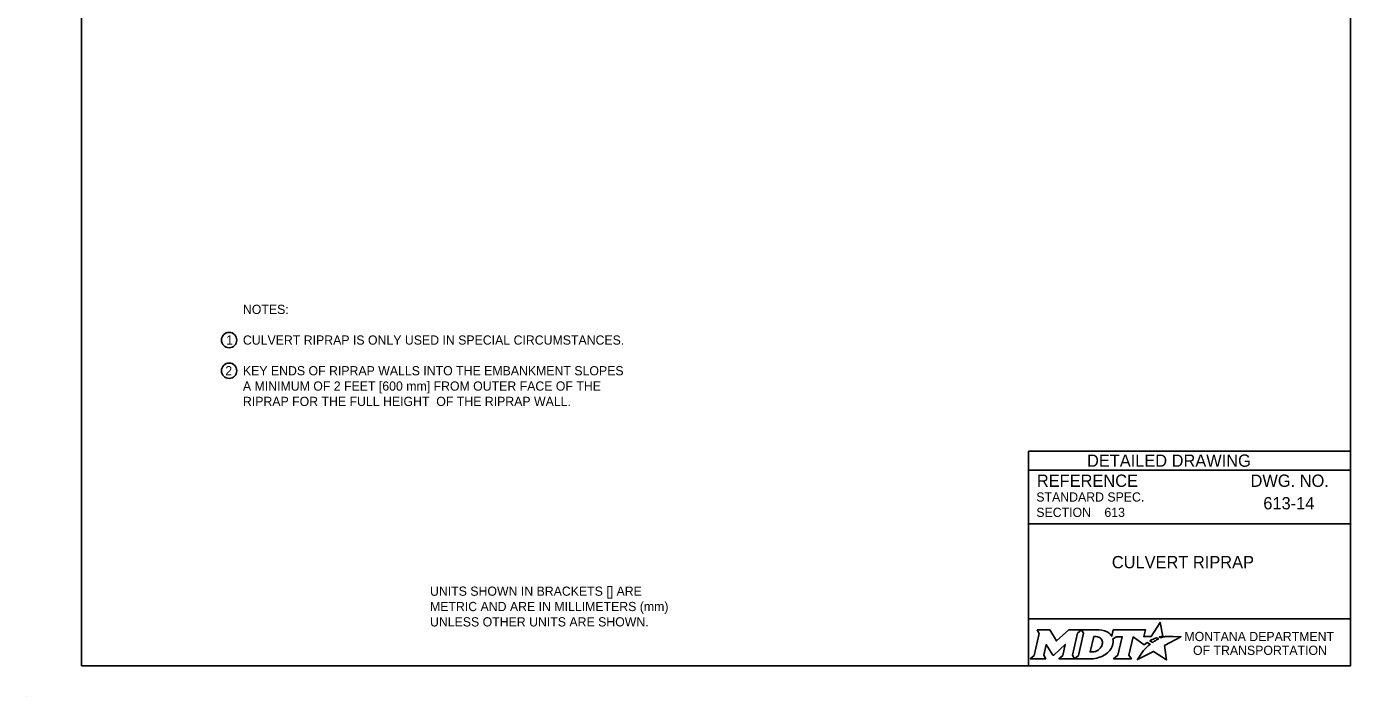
# Model space of a CAD drawing. Extents: x 49991.4 to 50021, y 49987.6 to 50011.4.
# Drawn here: x 49999.98 to 50008.61, y 49999.86 to 50004.23 of the extents above; entities that cross this region are included whole.
import ezdxf

# ---------------------------------------------------------------- set-up
doc = ezdxf.new("R2010")
doc.units = 0
doc.layers.add('Level 1', color=7, linetype='Continuous')
doc.layers.add('Level 2', color=7, linetype='Continuous')

msp = doc.modelspace()

# ---------------------------------------------------------------- linework, layer by layer
at = {"layer": 'Level 1'}
msp.add_line((49999.9766, 49999.8624), (49999.9766, 49999.8624), dxfattribs=at)
msp.add_lwpolyline([(50008.6146, 50011.2628), (50000.3356, 50011.2628), (50000.3356, 50000.0624), (50008.6146, 50000.0624)], close=True, dxfattribs=at)
at = {"layer": 'Level 2'}
for p, q in [((50008.6146, 50001.4624), (50006.5146, 50001.4624)), ((50006.5146, 50001.4624), (50006.5146, 50000.0624)), ((50008.6146, 50001.3374), (50006.5146, 50001.3374)), ((50008.2507, 50001.1223), (50008.2507, 50001.1223)), ((50008.6146, 50000.9874), (50006.5146, 50000.9874)), ((50007.0089, 50001.0629), (50007.0089, 50001.0629)), ((50007.5646, 50000.7383), (50007.5646, 50000.7383)), ((50008.6146, 50000.3693), (50006.5146, 50000.3693))]:
    msp.add_line(p, q, dxfattribs=at)
for points in [[(50006.5701, 50000.2974), (50006.5842, 50000.274), (50006.5507, 50000.1307), (50006.525, 50000.1082), (50006.6266, 50000.1082), (50006.6131, 50000.131), (50006.6293, 50000.2011), (50006.673, 50000.1321), (50006.6783, 50000.1321), (50006.7534, 50000.2016), (50006.737, 50000.1305), (50006.7123, 50000.1085), (50006.8139, 50000.1085), (50006.8001, 50000.1318), (50006.8333, 50000.2742)], [(50006.8333, 50000.2742), (50006.8586, 50000.2974), (50006.7762, 50000.2974), (50006.6966, 50000.2244), (50006.6521, 50000.2971), (50006.5701, 50000.2974)], [(50006.9722, 50000.2974), (50006.8586, 50000.2974), (50006.8733, 50000.2745), (50006.8394, 50000.1307), (50006.8139, 50000.1085), (50006.9245, 50000.1085)], [(50007.3771, 50000.2447), (50007.3668, 50000.2503), (50007.3784, 50000.2531), (50007.39, 50000.2551), (50007.3726, 50000.3452), (50007.3131, 50000.2539), (50007.2658, 50000.2532), (50007.2761, 50000.2973), (50007.0669, 50000.2974), (50007.0568, 50000.2549), (50007.051, 50000.2632)], [(50006.9962, 50000.2107), (50006.995, 50000.2026), (50006.9918, 50000.1933), (50006.9876, 50000.1851), (50006.982, 50000.1776), (50006.9755, 50000.1707), (50006.9676, 50000.1644), (50006.9593, 50000.1597), (50006.9502, 50000.1558), (50006.9411, 50000.1535), (50006.9319, 50000.1526), (50006.916, 50000.1526), (50006.9396, 50000.2526), (50006.9556, 50000.2526), (50006.9632, 50000.252), (50006.9708, 50000.2501), (50006.9774, 50000.2471), (50006.9835, 50000.2429), (50006.9883, 50000.2379), (50006.992, 50000.2319), (50006.9947, 50000.2257), (50006.9963, 50000.2183), (50006.9963, 50000.2153), (50006.9962, 50000.2107)], [(50007.0636, 50000.2383), (50007.0882, 50000.2514), (50007.1251, 50000.2514), (50007.0965, 50000.1309), (50007.069, 50000.1082), (50007.1852, 50000.1082), (50007.1682, 50000.1311), (50007.1964, 50000.2513), (50007.2677, 50000.1996), (50007.2888, 50000.2147), (50007.3085, 50000.2038)], [(50007.2527, 50000.1479), (50007.2374, 50000.1235), (50007.2327, 50000.116), (50007.2269, 50000.1074), (50007.2246, 50000.1031), (50007.3299, 50000.1562), (50007.4138, 50000.1011), (50007.4007, 50000.1938), (50007.5076, 50000.2522), (50007.4583, 50000.253), (50007.4282, 50000.2534), (50007.4074, 50000.2537), (50007.4006, 50000.2522), (50007.3957, 50000.251), (50007.3873, 50000.2487), (50007.3771, 50000.2447)], [(50007.3267, 50000.2171), (50007.3243, 50000.2154), (50007.306, 50000.225), (50007.3163, 50000.2307), (50007.3204, 50000.2329), (50007.329, 50000.2369), (50007.3347, 50000.2395), (50007.3426, 50000.2425), (50007.3499, 50000.2452), (50007.3617, 50000.2378), (50007.3577, 50000.2357), (50007.3531, 50000.2332), (50007.3489, 50000.231), (50007.3439, 50000.2281), (50007.342, 50000.227), (50007.3393, 50000.2254), (50007.3368, 50000.224), (50007.3345, 50000.2224), (50007.3319, 50000.2206), (50007.3292, 50000.2188), (50007.3267, 50000.2171)], [(50006.9702, 50000.1158), (50006.9786, 50000.1184), (50006.9916, 50000.1238), (50007.012, 50000.1348)], [(50007.2666, 50000.164), (50007.2666, 50000.164)]]:
    msp.add_lwpolyline(points, dxfattribs=at)
for centre in [(50001.2987, 50002.186), (50001.2987, 50001.986)]:
    msp.add_circle(centre, 0.05, dxfattribs=at)
for centre, radius, start, end in [((50006.9953, 50000.219), 0.0709, 339.53292, 15.85821), ((50006.9513, 50000.2363), 0.1183, 300.91025, 339.13831)]:
    msp.add_arc(centre, radius, start, end, dxfattribs=at)
for centre, major_axis, ratio, start_param, end_param in [((50006.9701, 50000.25), (0.0834, -0.0037), 0.568097, 0.61298, 1.570796), ((50007.0257, 50000.2573), (0.0361, -0.0295), 0.469099, 1.225588, 1.570796), ((50007.2974, 50000.1941), (-0.0112, -0.0097), 0.021651, 3.157348, 6.283185), ((50006.9248, 50000.2568), (0, 0.1484), 0.987302, 3.139398, 3.456847), ((50007.2597, 50000.1559), (-0.00694, -0.00806), 0.008222, 0, 3.137361), ((50007.2764, 50000.1742), (-0.0098, -0.0102), 0.016458, 3.141593, 6.279097)]:
    msp.add_ellipse(centre, major_axis=major_axis, ratio=ratio, start_param=start_param, end_param=end_param, dxfattribs=at)

# ---------------------------------------------------------------- texts
for s, height, p in [('NOTES:', 0.06, (50001.3887, 50002.356)), ('1', 0.06, (50001.2789, 50002.156)), ('CULVERT RIPRAP IS ONLY USED IN SPECIAL CIRCUMSTANCES.', 0.06, (50001.3887, 50002.156)), ('2', 0.06, (50001.2735, 50001.956)), ('KEY ENDS OF RIPRAP WALLS INTO THE EMBANKMENT SLOPES', 0.06, (50001.3887, 50001.956)), ('A MINIMUM OF 2 FEET [600 mm] FROM OUTER FACE OF THE', 0.06, (50001.3887, 50001.856)), ('RIPRAP FOR THE FULL HEIGHT  OF THE RIPRAP WALL.', 0.06, (50001.3887, 50001.756)), ('DETAILED DRAWING', 0.0799, (50006.8956, 50001.3599)), ('REFERENCE', 0.08, (50006.5682, 50001.229)), ('DWG. NO.', 0.08, (50007.9624, 50001.229)), ('STANDARD SPEC.', 0.06, (50006.5649, 50001.133)), ('613-14', 0.08, (50008.0456, 50001.0823)), ('SECTION', 0.06, (50006.5649, 50001.033)), ('613', 0.06, (50007.0089, 50001.0329)), ('CULVERT RIPRAP', 0.08, (50007.0574, 50000.6983)), ('UNITS SHOWN IN BRACKETS [] ARE ', 0.06, (50002.6092, 50000.519)), ('METRIC AND ARE IN MILLIMETERS (mm) ', 0.06, (50002.6092, 50000.419)), ('UNLESS OTHER UNITS ARE SHOWN.', 0.06, (50002.6092, 50000.319)), ('MONTANA DEPARTMENT', 0.06, (50007.5308, 50000.2236)), ('OF TRANSPORTATION', 0.06, (50007.587, 50000.1336))]:
    msp.add_text(s, height=height, dxfattribs=at).set_placement(p)

doc.saveas('drawing.dxf')
